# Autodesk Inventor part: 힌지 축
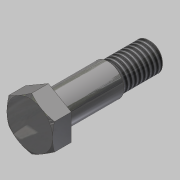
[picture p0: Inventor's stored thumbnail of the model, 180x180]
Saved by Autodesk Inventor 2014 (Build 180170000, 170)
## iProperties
Created: 2019-09
Part Number: 힌지 축
Material: 스테인리스강
Document SubType Name: Modeling
Designer: mduedu
Density: 8.08 g/cm^3
Appearance: 반광택
Mass: 19.8099 g
Surface Area: 13.175 cm^2
Volume: 2.45172 cm^3
Author: mduedu
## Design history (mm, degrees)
sketch "스케치1"
  geometry: C1 r 4 at (0, 0); 1 further point
  constraints: 1 centre point, 1 coincident
  dimensions: "d0" = 8 diameter of C1
extrude "돌출1" new body sketch "스케치1" distance "d1" = 29; taper "d2" = 0 deg
sketch "스케치2"
  geometry: C1 r 4.5 at (0, 0); 1 further point
  constraints: 1 centre point, 1 coincident
  dimensions: "d3" = 9 diameter of C1
extrude "돌출2" join sketch "스케치2" distance "d4" = 17.5; taper "d5" = 0 deg
sketch "스케치3"
  geometry: L1 (0, 7.506)-(6.5, 3.753); L2 (6.5, 3.753)-(6.5, -3.753); L3 (6.5, -3.753)-(0, -7.506); L4 (0, -7.506)-(-6.5, -3.753); L5 (-6.5, -3.753)-(-6.5, 3.753); L6 (-6.5, 3.753)-(0, 7.506); C1 r 6.5 at (0, 0); 2 further points
  constraints: 12 end point, 2 coincident, 1 centre point, 1 tangent, 1 vertical alignment, 13 other
  dimensions: "d6" = 6.5 radius of C1
extrude "돌출3" join sketch "스케치3" distance "d8" = 5.3; taper "d9" = 0 deg
sketch "스케치4"
  geometry: L1 (-4, 11.5)-(-4.5, 11.5) reference; L2 (-4.5, 11.5)-(-4.5, 29) reference; L3 (-4.5, 29)-(-7.506, 29) reference; L4 (-7.506, 29)-(-7.506, 34.3) reference; L5 (-7.506, 34.3)-(7.506, 34.3) reference; L6 (7.506, 34.3)-(7.506, 29) reference; L7 (7.506, 29)-(4.5, 29) reference; L8 (4.5, 29)-(4.5, 11.5) reference; L9 (4.5, 11.5)-(4, 11.5) reference; L10 (4, 11.5)-(4, 0) reference; L11 (4, 0)-(-4, 0) reference; L12 (-4, 0)-(-4, 11.5) reference; L13 (0, 0)-(0, 34.3); L14 (7.506, 34.3)-(7.506, 33.746); L15 (6.506, 34.3)-(7.506, 33.746); L16 (7.506, 34.3)-(6.506, 34.3); L17 (4.5, 29)-(4, 29); L18 (4, 29)-(4, 28.5); L19 (4, 28.5)-(4.5, 28.5); L20 (4.5, 28.5)-(4.5, 29)
  constraints: 16 end point, 2 parallel, 2 perpendicular, 2 point on line, 1 horizontal, 1 midpoint
  dimensions: "d10" = 1 distance of L5.end L15.start; "d11" = 29 deg angle of L15 L5; "d12" = 0.5 distance of L19.end L7.end; "d13" = 0.5 distance of L18.end L19.end
revolve "회전1" sketch "스케치4" stored, may be unused: angle "d14" = 90 deg
feature "스레드1" dims "d15" = 10, "d16" = 0
chamfer "모따기1" distance "d17" = 0.5; stored, may be unused: second distance "d18" = 2, angle "d19" = 45 deg
chamfer "모따기2" distance "d20" = 0.5; stored, may be unused: second distance "d21" = 2, angle "d22" = 45 deg
node "솔리드1"
node "절단 모서리 투영1"
